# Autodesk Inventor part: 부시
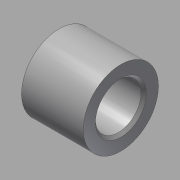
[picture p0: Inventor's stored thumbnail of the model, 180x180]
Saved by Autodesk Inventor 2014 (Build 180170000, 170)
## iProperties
Created: 2016-10
Part Number: 부시
Material: 강철, 연강
Document SubType Name: Modeling
Designer: mduedu
Density: 1 g/cm^3
Appearance: Steel
Author: mduedu
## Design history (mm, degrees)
sketch "스케치1"
  geometry: C1 r 14 at (0, 0); C2 r 8.5 at (0, 0); 1 further point
  constraints: 2 centre point, 2 coincident
  dimensions: "d0" = 28 diameter of C1; "d1" = 17 diameter of C2
extrude "돌출1" new body sketch "스케치1" distance "d2" = 23; taper "d3" = 0 deg
chamfer "모따기1" distance "d4" = 1; stored, may be unused: second distance "d5" = 2, angle "d6" = 45 deg
node "솔리드1"
